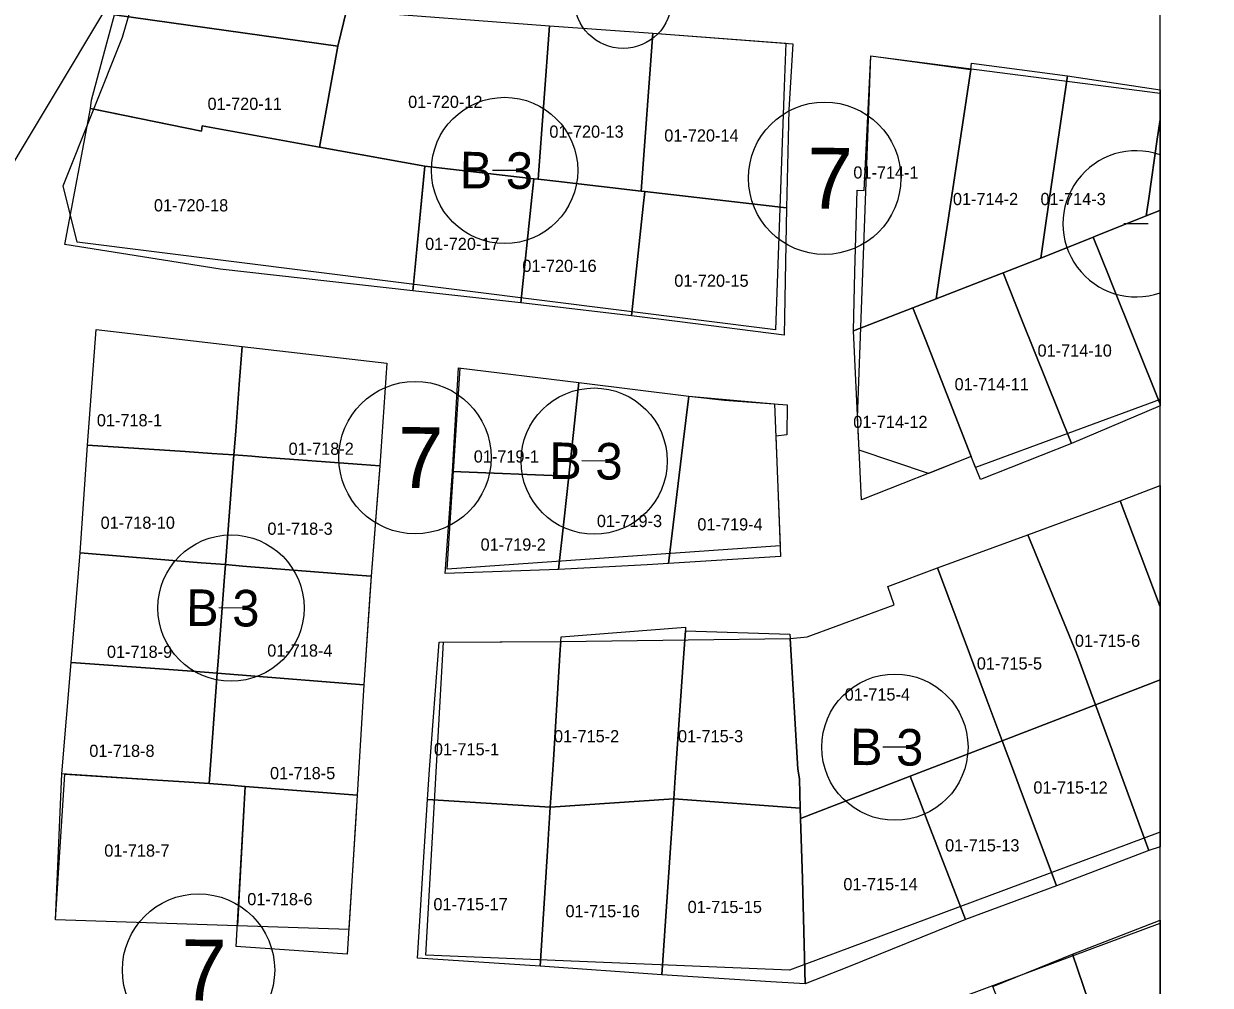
# Model space of a CAD drawing. Extents: x 413946 to 415528, y 4453939 to 4454944.
# Drawn here: x 414923.9 to 415021.3, y 4454767.4 to 4454846.3 of the extents above; entities that cross this region are included whole.
import ezdxf

# ---------------------------------------------------------------- set-up
doc = ezdxf.new("R2010")
doc.units = 0
for name, color, linetype in [('0_KADASTRO', 7, 'Continuous'), ('0_ÖNERİ_LEJAND', 7, 'Continuous'), ('Level 27', 7, 'Continuous'), ('Level 29', 7, 'Continuous'), ('Level 32', 7, 'Continuous'), ('Level 58', 7, 'Continuous'), ('Level 62', 7, 'Continuous')]:
    doc.layers.add(name, color=color, linetype=linetype)

msp = doc.modelspace()

# ---------------------------------------------------------------- linework, layer by layer
at = {"layer": '0_KADASTRO'}
for points in [[(414931.34, 4454847.01), (414935.98, 4454864.35), (414947.02, 4454862), (414953.82, 4454861.5), (414950.38, 4454847.34), (414949.66, 4454844.42)], [(414929.36, 4454839.31), (414929.44, 4454840.01), (414930.74, 4454844.79), (414931.34, 4454847.01), (414949.66, 4454844.42), (414948.17, 4454836.15), (414940.016, 4454837.623), (414938.54, 4454837.89), (414938.46, 4454837.45), (414929.634, 4454839.254)], [(414948.17, 4454836.15), (414949.66, 4454844.42), (414950.38, 4454847.34), (414967.03, 4454846.1), (414966.09, 4454833.51), (414965.75, 4454833.54), (414957.74, 4454834.47), (414956.81, 4454834.58)], [(414966.09, 4454833.51), (414967.03, 4454846.1), (414975.51, 4454845.48), (414974.55, 4454832.53), (414967.54, 4454833.35)], [(414974.55, 4454832.53), (414975.51, 4454845.48), (414986.99, 4454844.63), (414986.66, 4454839.21), (414986.49, 4454831.16), (414974.86, 4454832.5)], [(414991.98, 4454821.08), (414992.1, 4454825.9), (414992.27, 4454832.6), (414992.86, 4454832.58), (414993.39, 4454843.64), (415001.6, 4454842.52), (414999.91, 4454831.27), (414999.79, 4454830.53), (414999.05, 4454825.59), (414998.77, 4454823.71), (414996.85, 4454822.97)], [(414998.77, 4454823.71), (414999.05, 4454825.59), (414999.79, 4454830.53), (414999.91, 4454831.27), (415001.6, 4454842.52), (415001.67, 4454843.04), (415009.55, 4454841.98), (415007.79, 4454830.1), (415007.34, 4454827.03), (415004.25, 4454825.83), (415002.84, 4454825.29)], [(414929.36, 4454839.31), (414938.46, 4454837.45), (414938.54, 4454837.89), (414948.17, 4454836.15), (414956.81, 4454834.58), (414955.82, 4454824.36), (414940, 4454826.14), (414927.25, 4454828.16)], [(414955.82, 4454824.36), (414955.87, 4454824.878), (414956.59, 4454832.35), (414956.81, 4454834.58), (414957.74, 4454834.47), (414965.75, 4454833.54), (414965.59, 4454832), (414964.67, 4454823.37)], [(414964.67, 4454823.37), (414965.59, 4454832), (414965.75, 4454833.54), (414966.09, 4454833.51), (414967.54, 4454833.35), (414974.55, 4454832.53), (414974.86, 4454832.5), (414974.73, 4454831.29), (414973.75, 4454822.31)], [(414973.75, 4454822.31), (414974.73, 4454831.29), (414974.86, 4454832.5), (414986.49, 4454831.16), (414986.43, 4454828.19), (414986.29, 4454820.72), (414977.72, 4454821.81)], [(414996.85, 4454822.97), (414998.77, 4454823.71), (415002.84, 4454825.29), (415004.25, 4454825.83), (415005.77, 4454822.03), (415009.86, 4454811.83), (415002.4, 4454808.88), (415001.64, 4454810.77), (414997.88, 4454820.35)], [(414991.98, 4454821.08), (414996.85, 4454822.97), (414997.88, 4454820.35), (415001.64, 4454810.77), (414992.64, 4454807.2)], [(414929.13, 4454811.7), (414929.82, 4454821.17), (414941.8, 4454819.79), (414941.57, 4454816.68), (414941.28, 4454812.85), (414941.13, 4454810.89), (414939.33, 4454811.01), (414937.14, 4454811.17)], [(414941.13, 4454810.89), (414941.28, 4454812.85), (414941.57, 4454816.68), (414941.8, 4454819.79), (414953.67, 4454818.42), (414953.2, 4454811.2), (414953.12, 4454810), (414951.62, 4454810.11), (414943.45, 4454810.72), (414942.6, 4454810.79)], [(414959.06, 4454809.53), (414959.57, 4454818.03), (414969.45, 4454816.83), (414968.61, 4454809.14)], [(414967.78, 4454801.48), (414968.232, 4454805.65), (414968.61, 4454809.14), (414969.45, 4454816.83), (414978.47, 4454815.71), (414977.982, 4454811.719), (414976.79, 4454801.98), (414975.06, 4454801.88)], [(414976.79, 4454801.98), (414977.982, 4454811.719), (414978.47, 4454815.71), (414981.39, 4454815.39), (414986.54, 4454814.99), (414986.52, 4454812.53), (414985.6, 4454812.44), (414986, 4454802.55)], [(414928.51, 4454802.85), (414929.13, 4454811.7), (414937.14, 4454811.17), (414939.33, 4454811.01), (414941.13, 4454810.89), (414940.45, 4454801.89), (414938.45, 4454802.05)], [(414940.45, 4454801.89), (414941.13, 4454810.89), (414942.6, 4454810.79), (414943.45, 4454810.72), (414951.62, 4454810.11), (414953.12, 4454810), (414953.01, 4454808.65), (414952.4, 4454800.94), (414950.9, 4454801.06), (414941.85, 4454801.78)], [(414959.06, 4454809.53), (414968.61, 4454809.14), (414968.232, 4454805.65), (414967.78, 4454801.48), (414958.48, 4454801.16)], [(414998.88, 4454801.62), (415006.29, 4454804.34), (415010.29, 4454794.63), (415011.83, 4454790.4), (415004.18, 4454787.45), (415002.96, 4454790.73), (415002.35, 4454792.34)], [(414927.79, 4454793.86), (414928.51, 4454802.85), (414938.45, 4454802.05), (414940.45, 4454801.89), (414940.34, 4454800.55), (414939.87, 4454794.33), (414939.76, 4454792.99), (414937.67, 4454793.14), (414935.78, 4454793.28)], [(414939.76, 4454792.99), (414939.87, 4454794.33), (414940.34, 4454800.55), (414940.45, 4454801.89), (414941.85, 4454801.78), (414950.9, 4454801.06), (414952.4, 4454800.94), (414952.3, 4454799.45), (414951.8, 4454792.03), (414941.49, 4454792.85)], [(414986.77, 4454795.82), (414988.17, 4454795.96), (414995.31, 4454798.6), (414994.79, 4454800.11), (414998.88, 4454801.62), (415002.35, 4454792.34), (415002.96, 4454790.73), (415004.18, 4454787.45), (414996.63, 4454784.54), (414987.63, 4454781.06), (414987.59, 4454781.91), (414987.55, 4454784.32), (414987.4, 4454785.11)], [(414967.1, 4454781.99), (414967.27, 4454784.67), (414967.35, 4454785.88), (414967.92, 4454794.93), (414967.97, 4454795.58), (414967.99, 4454795.96), (414978.2, 4454796.76), (414978.18, 4454796.46), (414978.03, 4454794.24), (414977.41, 4454785.22), (414977.357, 4454784.432), (414977.24, 4454782.67)], [(414977.24, 4454782.67), (414977.357, 4454784.432), (414977.41, 4454785.22), (414978.03, 4454794.24), (414978.18, 4454796.46), (414986.75, 4454796.19), (414986.77, 4454795.82), (414987.4, 4454785.11), (414987.55, 4454784.32), (414987.59, 4454781.91)], [(414957.01, 4454782.62), (414957.19, 4454785.08), (414957.98, 4454795.52), (414967.97, 4454795.58), (414967.92, 4454794.93), (414967.35, 4454785.88), (414967.27, 4454784.67), (414967.1, 4454781.99)], [(414927.02, 4454784.73), (414927.79, 4454793.86), (414935.78, 4454793.28), (414937.67, 4454793.14), (414939.76, 4454792.99), (414939.09, 4454783.93), (414937.05, 4454784.07), (414934.85, 4454784.22)], [(414939.09, 4454783.93), (414939.76, 4454792.99), (414941.49, 4454792.85), (414951.8, 4454792.03), (414951.25, 4454782.98), (414942.05, 4454783.7), (414940.88, 4454783.8)], [(415004.18, 4454787.45), (415011.83, 4454790.4), (415013.2, 4454786.66), (415013.63, 4454785.51), (415016.23, 4454778.45), (415008.63, 4454775.53), (415005.58, 4454783.72), (415005.11, 4454784.97)], [(414996.63, 4454784.54), (415004.18, 4454787.45), (415005.11, 4454784.97), (415005.58, 4454783.72), (415008.63, 4454775.53), (415001.16, 4454772.77), (414997.97, 4454781.04), (414997.52, 4454782.21)], [(414926.5, 4454772.76), (414927.269, 4454784.714), (414934.85, 4454784.22), (414937.05, 4454784.07), (414939.09, 4454783.93), (414940.88, 4454783.8), (414942.05, 4454783.7), (414941.94, 4454781.71), (414941.423, 4454772.267)], [(414941.33, 4454770.57), (414941.94, 4454781.71), (414942.05, 4454783.7), (414951.25, 4454782.98), (414951.13, 4454781.08), (414950.43, 4454769.93)], [(414987.63, 4454781.06), (414996.63, 4454784.54), (414997.52, 4454782.21), (414997.97, 4454781.04), (415001.16, 4454772.77), (414991.57, 4454768.91), (414988.02, 4454767.49), (414987.8, 4454776.12)], [(414966.27, 4454768.95), (414966.9, 4454778.82), (414966.96, 4454779.82), (414967.1, 4454781.99), (414977.24, 4454782.67), (414977.04, 4454779.84), (414977.01, 4454779.44), (414976.24, 4454768.23)], [(414976.24, 4454768.23), (414977.01, 4454779.44), (414977.04, 4454779.84), (414977.24, 4454782.67), (414987.59, 4454781.91), (414987.63, 4454781.06), (414987.8, 4454776.12), (414988.02, 4454767.49), (414985.2, 4454767.67)], [(414957.01, 4454782.62), (414967.1, 4454781.99), (414966.96, 4454779.82), (414966.9, 4454778.82), (414966.27, 4454768.95), (414956.19, 4454769.6), (414956.77, 4454778.76)], [(415003.42, 4454767.28), (415009.95, 4454769.93), (415013.05, 4454760.85), (415013.86, 4454758.48), (415010.35, 4454757.23), (415007.72, 4454756.29), (415007.39, 4454757.15), (415005.99, 4454760.71), (415004.85, 4454763.61)]]:
    msp.add_lwpolyline(points, close=True, dxfattribs=at)
for points in [[(415017.152, 4454838.423), (415016.91, 4454836.79), (415016.21, 4454831.94), (415016.01, 4454830.5), (415011.84, 4454828.84), (415011.65, 4454828.76), (415007.34, 4454827.03), (415007.79, 4454830.1), (415009.55, 4454841.98), (415017.152, 4454840.833)], [(415017.152, 4454840.833), (415017.152, 4454838.423)], [(415017.152, 4454830.963), (415017.12, 4454830.95), (415016.01, 4454830.5), (415016.21, 4454831.94), (415016.91, 4454836.79), (415017.152, 4454838.423)], [(415017.152, 4454838.423), (415017.152, 4454830.963)], [(415017.152, 4454815.061), (415013.1, 4454825.15), (415012.95, 4454825.51), (415011.65, 4454828.76), (415011.84, 4454828.84), (415016.01, 4454830.5), (415017.12, 4454830.95), (415017.152, 4454830.963)], [(415017.152, 4454830.963), (415017.152, 4454815.061)], [(415017.152, 4454814.919), (415009.86, 4454811.83), (415005.77, 4454822.03), (415004.25, 4454825.83), (415007.34, 4454827.03), (415011.65, 4454828.76), (415012.95, 4454825.51), (415013.1, 4454825.15), (415017.152, 4454815.061)], [(415017.152, 4454815.061), (415017.152, 4454814.919)], [(415017.152, 4454798.422), (415013.86, 4454807.14), (415017.152, 4454808.386)], [(415017.152, 4454808.386), (415017.152, 4454798.422)], [(415017.152, 4454792.448), (415011.83, 4454790.4), (415010.29, 4454794.63), (415006.29, 4454804.34), (415013.86, 4454807.14), (415017.152, 4454798.422)], [(415017.152, 4454798.422), (415017.152, 4454792.448)], [(415017.152, 4454778.753), (415016.23, 4454778.45), (415013.63, 4454785.51), (415013.2, 4454786.66), (415011.83, 4454790.4), (415017.152, 4454792.448)], [(415017.152, 4454792.448), (415017.152, 4454778.753)], [(415017.152, 4454759.74), (415014.51, 4454758.73), (415013.86, 4454758.48), (415013.05, 4454760.85), (415009.95, 4454769.93), (415017.152, 4454772.737)], [(415017.152, 4454772.737), (415017.152, 4454759.74)]]:
    msp.add_lwpolyline(points, dxfattribs=at)
at = {"layer": '0_ÖNERİ_LEJAND'}
msp.add_lwpolyline([(415017.152, 4454915.569), (415467.6, 4454915.569), (415467.6, 4454735.447), (415017.152, 4454735.447)], close=True, dxfattribs=at)
at = {"layer": 'Level 27'}
for p, q in [((414994.218, 4454843.533), (415017.152, 4454840.566)), ((414985.493, 4454815.083), (414985.965, 4454803.423)), ((415017.152, 4454815.452), (415002, 4454809.874))]:
    msp.add_line(p, q, dxfattribs=at)
for points in [[(414953.82, 4454861.5), (414950.38, 4454847.34), (414967.03, 4454846.1), (414975.51, 4454845.48), (414986.423, 4454844.672)], [(414941.42, 4454772.27), (414926.5, 4454772.76), (414927.02, 4454784.73), (414927.79, 4454793.86), (414928.51, 4454802.85), (414929.13, 4454811.7), (414929.82, 4454821.17)], [(414929.82, 4454821.17), (414941.8, 4454819.79), (414953.67, 4454818.42), (414953.12, 4454810), (414952.4, 4454800.94), (414951.8, 4454792.03), (414951.25, 4454782.98), (414950.558, 4454771.97)], [(414959.57, 4454818.03), (414969.45, 4454816.83), (414978.47, 4454815.71), (414985.493, 4454815.083)], [(415002, 4454809.874), (415001.64, 4454810.77), (414998.135, 4454809.38)], [(414958.327, 4454795.522), (414967.97, 4454795.58), (414986.77, 4454795.82), (414988.17, 4454795.96), (414995.31, 4454798.6), (414994.79, 4454800.11), (414998.88, 4454801.62), (415006.29, 4454804.34), (415013.86, 4454807.14), (415017.152, 4454808.386)], [(415017.152, 4454779.94), (414986.721, 4454768.62)], [(414974.141, 4454762.513), (414988.14, 4454761.68), (415017.152, 4454772.472)]]:
    msp.add_lwpolyline(points, dxfattribs=at)
at = {"layer": 'Level 29'}
for p, q in [((414986.423, 4454844.672), (414986.295, 4454841.127)), ((414992.32, 4454813.926), (414993.39, 4454843.64)), ((414986.295, 4454841.127), (414985.576, 4454821.144)), ((414992.446, 4454811.286), (414992.32, 4454813.926)), ((414950.558, 4454771.97), (414941.42, 4454772.27))]:
    msp.add_line(p, q, dxfattribs=at)
for points in [[(414928.272, 4454828.35), (414927.12, 4454832.972), (414931.994, 4454845.153), (414944.09, 4454886.752), (414947.697, 4454888.335)], [(414985.576, 4454821.144), (414928.272, 4454828.35)], [(414985.965, 4454803.423), (414958.63, 4454801.529), (414959.697, 4454818.015)], [(414998.135, 4454809.38), (414992.446, 4454811.286)], [(414986.721, 4454768.62), (414956.876, 4454769.865), (414958.327, 4454795.522)]]:
    msp.add_lwpolyline(points, dxfattribs=at)
at = {"layer": 'Level 32'}
for p, q in [((414964.349, 4454834.22), (414962.349, 4454834.24)), ((415016.172, 4454829.841), (415014.173, 4454829.861)), ((414971.697, 4454810.375), (414969.697, 4454810.396)), ((414941.897, 4454798.323), (414939.897, 4454798.343)), ((414996.379, 4454786.907), (414994.379, 4454786.928))]:
    msp.add_line(p, q, dxfattribs=at)
msp.add_lwpolyline([(415017.152, 4454824.187), (415017.152, 4454835.515)], dxfattribs=at)
for centre in [(414963.349, 4454834.23), (414970.697, 4454810.386), (414940.897, 4454798.333), (414995.379, 4454786.918)]:
    msp.add_circle(centre, 6, dxfattribs=at)
msp.add_arc((415015.172, 4454829.851), 6, 70.74056, 289.25944, dxfattribs=at)
at = {"layer": 'Level 58'}
for centre, radius in [((414973.069, 4454848.242), 4), ((414989.61, 4454833.594), 6.25), ((414955.997, 4454810.673), 6.25), ((414938.23, 4454768.636), 6.25)]:
    msp.add_circle(centre, radius, dxfattribs=at)
at = {"layer": 'Level 62'}
msp.add_lwpolyline([(414930.922, 4454848.029), (414920.832, 4454831.252)], dxfattribs=at)

# ---------------------------------------------------------------- texts
at = {"layer": '0_KADASTRO'}
for s, p in [('01-720-11', (414938.968, 4454839.2)), ('01-720-12', (414955.432, 4454839.357)), ('01-720-13', (414967.022, 4454836.917)), ('01-720-14', (414976.453, 4454836.604)), ('01-714-1', (414991.967, 4454833.566)), ('01-714-2', (415000.139, 4454831.388)), ('01-714-3', (415007.326, 4454831.388)), ('01-720-18', (414934.569, 4454830.872)), ('01-720-17', (414956.828, 4454827.704)), ('01-720-16', (414964.805, 4454825.907)), ('01-720-15', (414977.275, 4454824.688)), ('01-714-10', (415007.083, 4454818.957)), ('01-714-11', (415000.274, 4454816.191)), ('01-718-1', (414929.886, 4454813.237)), ('01-714-12', (414991.959, 4454813.101)), ('01-718-2', (414945.619, 4454810.901)), ('01-719-1', (414960.816, 4454810.268)), ('01-718-10', (414930.194, 4454804.832)), ('01-718-3', (414943.884, 4454804.342)), ('01-719-3', (414970.918, 4454804.973)), ('01-719-4', (414979.169, 4454804.697)), ('01-719-2', (414961.376, 4454803.042)), ('01-718-4', (414943.869, 4454794.346)), ('01-715-6', (415010.148, 4454795.149)), ('01-718-9', (414930.712, 4454794.244)), ('01-715-5', (415002.101, 4454793.289)), ('01-715-4', (414991.261, 4454790.745)), ('01-715-2', (414967.4, 4454787.317)), ('01-715-3', (414977.575, 4454787.317)), ('01-718-8', (414929.267, 4454786.119)), ('01-715-1', (414957.543, 4454786.246)), ('01-718-5', (414944.096, 4454784.291)), ('01-715-12', (415006.745, 4454783.115)), ('01-718-7', (414930.496, 4454777.934)), ('01-715-13', (414999.501, 4454778.365)), ('01-715-14', (414991.15, 4454775.18)), ('01-718-6', (414942.229, 4454773.952)), ('01-715-17', (414957.506, 4454773.535)), ('01-715-16', (414968.344, 4454772.971)), ('01-715-15', (414978.368, 4454773.311))]:
    msp.add_text(s, height=1, dxfattribs=at).set_placement(p)
at = {"layer": 'Level 32'}
for p in [(414959.65, 4454832.768), (414966.998, 4454808.923), (414937.198, 4454796.871), (414991.679, 4454785.455)]:
    msp.add_text('B 3', height=3, rotation=359.4141, dxfattribs=at).set_placement(p)
at = {"layer": 'Level 58'}
for p in [(414988.167, 4454831.109), (414954.554, 4454808.189), (414936.787, 4454766.151)]:
    msp.add_text('7', height=5, rotation=359.4141, dxfattribs=at).set_placement(p)

doc.saveas('drawing.dxf')
